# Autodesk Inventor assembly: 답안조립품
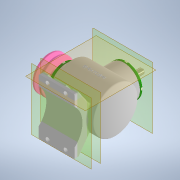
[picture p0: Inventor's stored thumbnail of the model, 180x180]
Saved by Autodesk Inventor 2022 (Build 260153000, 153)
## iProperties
Created: 2023-04
Part Number: 답안조립품
Document SubType Name: Assembly
Designer: Admin
Author: Admin
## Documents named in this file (17)
- C:\Users\Admin\Desktop\730411V1008\답안조립품.iam
- C:\Users\Admin\Desktop\730411V1008\본체.ipt
- C:\Users\Admin\Desktop\730411V1008\커버.ipt
- C:\Users\Admin\Desktop\730411V1008\베어링 6203.ipt
- C:\Users\Admin\Desktop\730411V1008\오일실 17 x 32 x 8.ipt
- C:\Users\Admin\Desktop\730411V1008\메인 축.ipt
- 메인 축.ipt
- C:\Users\Admin\Desktop\730411V1008\키 5 x 5 x 14.ipt
- C:\Users\Admin\Desktop\730411V1008\메인 베벨기어.ipt
- C:\Users\Admin\Desktop\730411V1008\서브 축.ipt
- 서브 축.ipt
- C:\Users\Admin\Desktop\730411V1008\키 4 x 4 x 14.ipt
- C:\Users\Admin\Desktop\730411V1008\서브 베벨기어.ipt
- C:\Users\Admin\Desktop\730411V1008\V-벨트풀리.ipt
- C:\Users\Admin\Desktop\730411V1008\볼트 M4 x 10.ipt
- C:\Users\Admin\Desktop\730411V1008\와셔 4 x 16.ipt
- C:\Users\Admin\Desktop\730411V1008\육각볼트 M4 x 8.ipt
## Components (1 placed, 1 different names)
1. V-벨트풀리:1
